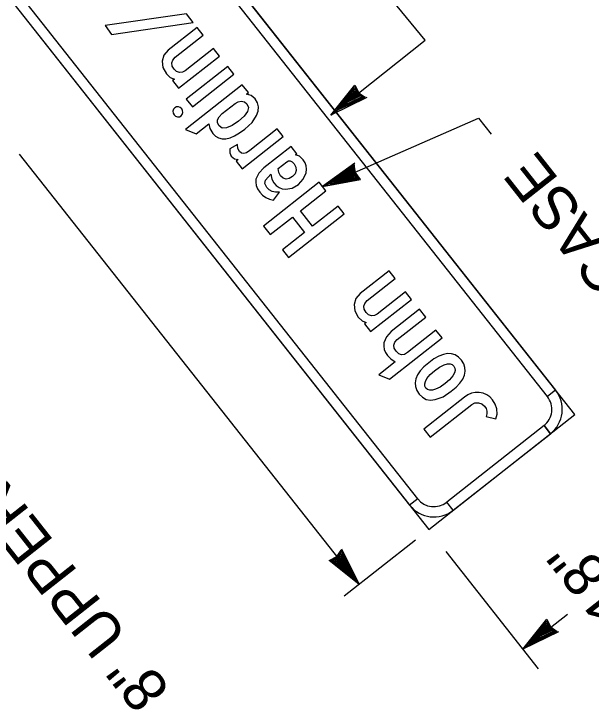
# Model space of a CAD drawing. Extents: x 671946 to 673995, y 1673066 to 1674936.
# Drawn here: x 672492.5 to 672548.4, y 1673764.2 to 1673831.7 of the extents above; entities that cross this region are included whole.
import ezdxf

# ---------------------------------------------------------------- set-up
doc = ezdxf.new("R2010")
doc.units = 0
doc.layers.add('C-ANNO-SYMB', color=7, linetype='Continuous')
doc.layers.add('Level 1', color=7, linetype='Continuous')

msp = doc.modelspace()

# ---------------------------------------------------------------- linework, layer by layer
at = {"layer": 'C-ANNO-SYMB'}
for p, q in [((672546.828, 1673792.897), (672468.821, 1673891.846)), ((672470.678, 1673889.49), (672544.97, 1673795.253)), ((672544.185, 1673794.634), (672469.893, 1673888.871)), ((672454.685, 1673880.702), (672532.692, 1673781.753)), ((672531.62, 1673784.728), (672457.328, 1673878.966)), ((672456.543, 1673878.347), (672530.835, 1673784.109)), ((672544.97, 1673795.253), (672544.185, 1673794.634)), ((672544.97, 1673795.253), (672544.185, 1673794.634)), ((672544.185, 1673794.634), (672544.185, 1673794.634)), ((672544.185, 1673794.634), (672544.185, 1673794.634)), ((672532.692, 1673781.753), (672546.828, 1673792.897)), ((672546.828, 1673792.897), (672546.828, 1673792.897)), ((672546.828, 1673792.897), (672546.828, 1673792.897)), ((672543.853, 1673791.825), (672534.429, 1673784.396)), ((672543.853, 1673791.825), (672544.472, 1673791.04)), ((672544.472, 1673791.04), (672543.853, 1673791.825)), ((672543.853, 1673791.825), (672544.472, 1673791.04)), ((672535.048, 1673783.611), (672544.472, 1673791.04)), ((672531.62, 1673784.728), (672530.835, 1673784.109)), ((672531.62, 1673784.728), (672530.835, 1673784.109)), ((672535.048, 1673783.611), (672534.429, 1673784.396)), ((672534.429, 1673784.396), (672534.429, 1673784.396)), ((672534.429, 1673784.396), (672534.429, 1673784.396)), ((672535.048, 1673783.611), (672534.429, 1673784.396))]:
    msp.add_line(p, q, dxfattribs=at)
for points in [[(672509.876, 1673830.886), (672509.215, 1673831.723), (672501.355, 1673830.605), (672501.971, 1673829.732)], [(672512.433, 1673827.642), (672511.85, 1673828.382), (672509.104, 1673826.218), (672508.832, 1673826.07), (672508.542, 1673826.045), (672508.264, 1673826.142), (672508.026, 1673826.356), (672507.841, 1673826.676), (672507.797, 1673826.977), (672507.897, 1673827.256), (672508.142, 1673827.517), (672510.849, 1673829.651), (672510.247, 1673830.415), (672507.455, 1673828.214), (672507.027, 1673827.725), (672506.859, 1673827.137), (672506.944, 1673826.516), (672507.271, 1673825.927), (672507.645, 1673825.569), (672508.048, 1673825.401), (672507.872, 1673825.263), (672508.463, 1673824.513)], [(672513.819, 1673825.883), (672513.219, 1673826.644), (672509.203, 1673823.478), (672509.803, 1673822.717)], [(672508.701, 1673821.848), (672508.819, 1673821.986), (672508.868, 1673822.163), (672508.849, 1673822.35), (672508.758, 1673822.52), (672508.612, 1673822.653), (672508.437, 1673822.719), (672508.257, 1673822.713), (672508.088, 1673822.626), (672507.963, 1673822.482), (672507.907, 1673822.302), (672507.925, 1673822.111), (672508.017, 1673821.936), (672508.166, 1673821.806), (672508.348, 1673821.749), (672508.536, 1673821.761)], [(672518.586, 1673819.836), (672518.003, 1673820.576), (672515.351, 1673818.474), (672515.041, 1673818.273), (672514.77, 1673818.19), (672514.539, 1673818.227), (672514.344, 1673818.385), (672514.207, 1673818.682), (672514.177, 1673819.076), (672513.41, 1673818.664), (672513.425, 1673818.255), (672513.562, 1673817.948), (672513.867, 1673817.693), (672514.231, 1673817.602), (672514.034, 1673817.447), (672514.617, 1673816.707)], [(672524.48, 1673812.36), (672523.897, 1673813.1), (672521.423, 1673811.149), (672520.256, 1673812.63), (672522.73, 1673814.58), (672522.081, 1673815.404), (672516.69, 1673811.154), (672517.339, 1673810.33), (672519.501, 1673812.034), (672520.668, 1673810.554), (672518.506, 1673808.85), (672519.089, 1673808.11)], [(672531.024, 1673804.06), (672530.441, 1673804.799), (672527.696, 1673802.635), (672527.424, 1673802.488), (672527.133, 1673802.462), (672526.856, 1673802.559), (672526.617, 1673802.773), (672526.432, 1673803.093), (672526.388, 1673803.394), (672526.489, 1673803.673), (672526.734, 1673803.934), (672529.441, 1673806.068), (672528.838, 1673806.832), (672526.047, 1673804.632), (672525.619, 1673804.142), (672525.45, 1673803.554), (672525.536, 1673802.933), (672525.863, 1673802.344), (672526.237, 1673801.986), (672526.639, 1673801.818), (672526.464, 1673801.68), (672527.055, 1673800.93)], [(672529.04, 1673800.93), (672528.578, 1673800.43), (672528.349, 1673799.839), (672528.33, 1673799.514), (672528.379, 1673799.199), (672528.501, 1673798.893), (672528.691, 1673798.601), (672529.01, 1673798.287), (672529.444, 1673798.002), (672527.866, 1673796.759), (672528.889, 1673796.315), (672533.971, 1673800.321), (672533.388, 1673801.061), (672530.643, 1673798.897), (672530.34, 1673798.72), (672530.051, 1673798.683), (672529.781, 1673798.785), (672529.523, 1673799.029), (672529.343, 1673799.34), (672529.301, 1673799.634), (672529.403, 1673799.909), (672529.643, 1673800.166), (672532.388, 1673802.33), (672531.785, 1673803.094)], [(672539.176, 1673792.48), (672539.298, 1673792.946), (672539.274, 1673793.438), (672539.133, 1673793.9), (672538.872, 1673794.321), (672538.603, 1673794.605), (672538.298, 1673794.82), (672537.958, 1673794.959), (672537.578, 1673795.029), (672537.196, 1673795.028), (672536.83, 1673794.953), (672536.483, 1673794.809), (672536.152, 1673794.593), (672532.201, 1673791.478), (672532.818, 1673790.695), (672536.847, 1673793.872), (672537.155, 1673794.028), (672537.498, 1673794.044), (672537.828, 1673793.932), (672538.088, 1673793.703), (672538.232, 1673793.474), (672538.305, 1673793.231), (672538.31, 1673792.976), (672538.246, 1673792.708)]]:
    msp.add_lwpolyline(points, close=True, dxfattribs=at)
for points in [[(672515.233, 1673824.1), (672514.628, 1673824.867), (672509.127, 1673820.529), (672510.147, 1673820.092), (672511.396, 1673821.076), (672511.483, 1673820.622), (672511.764, 1673820.15), (672512.032, 1673819.879), (672512.331, 1673819.703), (672512.667, 1673819.616), (672513.036, 1673819.624), (672513.443, 1673819.719), (672513.883, 1673819.909), (672514.359, 1673820.188), (672514.866, 1673820.558), (672515.569, 1673821.211), (672516.019, 1673821.871), (672516.174, 1673822.306), (672516.199, 1673822.723), (672516.099, 1673823.121), (672515.87, 1673823.499), (672515.5, 1673823.808), (672515.043, 1673823.951), (672515.233, 1673824.1)], [(672513.931, 1673823.048), (672514.212, 1673823.208), (672514.518, 1673823.264), (672514.838, 1673823.206), (672515.08, 1673823.011), (672515.222, 1673822.665), (672515.132, 1673822.269), (672514.817, 1673821.826), (672514.27, 1673821.331), (672513.634, 1673820.894), (672513.105, 1673820.671), (672512.688, 1673820.667), (672512.378, 1673820.88), (672512.228, 1673821.169), (672512.228, 1673821.464), (672512.38, 1673821.761), (672512.681, 1673822.062), (672513.931, 1673823.048)], [(672519.904, 1673818.166), (672519.346, 1673818.873), (672516.722, 1673816.804), (672516.215, 1673816.284), (672515.955, 1673815.723), (672515.929, 1673815.404), (672515.977, 1673815.089), (672516.106, 1673814.772), (672516.311, 1673814.461), (672516.592, 1673814.162), (672516.907, 1673813.932), (672517.262, 1673813.768), (672517.648, 1673813.672), (672518.221, 1673814.44), (672517.846, 1673814.441), (672517.512, 1673814.518), (672517.229, 1673814.673), (672516.992, 1673814.901), (672516.801, 1673815.283), (672516.859, 1673815.621), (672517.398, 1673816.19), (672517.48, 1673815.714), (672517.668, 1673815.348), (672517.915, 1673815.09), (672518.185, 1673814.904), (672518.484, 1673814.787), (672518.806, 1673814.738), (672519.442, 1673814.845), (672520.059, 1673815.204), (672520.537, 1673815.716), (672520.798, 1673816.332), (672520.847, 1673816.673), (672520.818, 1673816.996), (672520.716, 1673817.298), (672520.536, 1673817.58), (672520.159, 1673817.949), (672519.795, 1673818.08), (672519.904, 1673818.166)], [(672518.107, 1673816.749), (672518.936, 1673817.403), (672519.106, 1673817.489), (672519.28, 1673817.483), (672519.458, 1673817.386), (672519.639, 1673817.197), (672519.824, 1673816.871), (672519.858, 1673816.542), (672519.752, 1673816.233), (672519.502, 1673815.964), (672519.172, 1673815.765), (672518.866, 1673815.709), (672518.586, 1673815.798), (672518.328, 1673816.033), (672518.159, 1673816.356), (672518.107, 1673816.749)], [(672532.682, 1673797.918), (672532.221, 1673797.518), (672531.855, 1673797.122), (672531.592, 1673796.732), (672531.422, 1673796.35), (672531.358, 1673795.972), (672531.388, 1673795.602), (672531.52, 1673795.237), (672531.747, 1673794.881), (672532.068, 1673794.564), (672532.435, 1673794.368), (672532.85, 1673794.293), (672533.308, 1673794.338), (672534.067, 1673794.618), (672534.868, 1673795.145), (672535.338, 1673795.551), (672535.707, 1673795.946), (672535.979, 1673796.335), (672536.148, 1673796.716), (672536.223, 1673797.088), (672536.194, 1673797.454), (672536.068, 1673797.813), (672535.843, 1673798.163), (672535.558, 1673798.461), (672535.238, 1673798.667), (672534.89, 1673798.779), (672534.508, 1673798.796), (672534.1, 1673798.718), (672533.657, 1673798.546), (672533.187, 1673798.279), (672532.682, 1673797.918)], [(672533.251, 1673797.141), (672533.732, 1673797.477), (672534.183, 1673797.706), (672534.488, 1673797.794), (672534.747, 1673797.805), (672534.961, 1673797.739), (672535.125, 1673797.595), (672535.228, 1673797.4), (672535.242, 1673797.178), (672535.175, 1673796.929), (672535.018, 1673796.657), (672534.702, 1673796.272), (672534.267, 1673795.887), (672533.797, 1673795.559), (672533.35, 1673795.341), (672533.049, 1673795.254), (672532.79, 1673795.245), (672532.58, 1673795.312), (672532.413, 1673795.457), (672532.315, 1673795.648), (672532.298, 1673795.867), (672532.366, 1673796.111), (672532.512, 1673796.381), (672532.829, 1673796.762), (672533.251, 1673797.141)]]:
    msp.add_lwpolyline(points, dxfattribs=at)
for centre, radius, start, end in [((672542.614, 1673793.396), 3, 308.25039, 38.2506), ((672542.614, 1673793.396), 2, 308.25039, 38.2506), ((672533.191, 1673785.966), 2, 218.25075, 308.25039), ((672533.191, 1673785.966), 3, 218.25075, 308.25039)]:
    msp.add_arc(centre, radius, start, end, dxfattribs=at)
at = {"layer": 'Level 1'}
for p, q in [((672523.213, 1673821.923), (672525.533, 1673824.833)), ((672523.431, 1673822.159), (672525.514, 1673824.684)), ((672523.782, 1673822.435), (672525.512, 1673824.516)), ((672525.512, 1673824.516), (672525.65, 1673824.256)), ((672525.514, 1673824.684), (672525.856, 1673824.119)), ((672525.533, 1673824.833), (672525.925, 1673824.073)), ((672524.001, 1673822.535), (672525.555, 1673824.251)), ((672524.072, 1673822.658), (672525.514, 1673824.384)), ((672524.506, 1673822.998), (672525.5, 1673824.106)), ((672526.016, 1673823.745), (672524.506, 1673822.998)), ((672524.893, 1673823.267), (672525.464, 1673823.979)), ((672525.853, 1673823.784), (672524.893, 1673823.267)), ((672525.558, 1673824.119), (672525.052, 1673823.361)), ((672525.229, 1673823.563), (672525.494, 1673823.902)), ((672525.746, 1673823.834), (672525.229, 1673823.563)), ((672525.464, 1673823.979), (672525.746, 1673823.834)), ((672525.494, 1673823.902), (672525.576, 1673823.837)), ((672525.5, 1673824.106), (672525.853, 1673823.784)), ((672525.514, 1673824.384), (672526.195, 1673823.686)), ((672525.555, 1673824.251), (672526.016, 1673823.745)), ((672525.934, 1673823.848), (672525.558, 1673824.119)), ((672525.576, 1673823.837), (672525.934, 1673823.848)), ((672525.65, 1673824.256), (672526.195, 1673823.686)), ((672525.856, 1673824.119), (672526.527, 1673823.646)), ((672525.925, 1673824.073), (672526.167, 1673823.764)), ((672526.167, 1673823.764), (672526.481, 1673823.576)), ((672526.674, 1673823.628), (672523.213, 1673821.923)), ((672526.316, 1673823.614), (672523.473, 1673822.191)), ((672526.481, 1673823.576), (672523.633, 1673822.283)), ((672526.195, 1673823.686), (672524.001, 1673822.535)), ((672526.195, 1673823.686), (672524.072, 1673822.658)), ((672525.052, 1673823.361), (672524.799, 1673823.26)), ((672526.527, 1673823.646), (672526.307, 1673823.71)), ((672526.307, 1673823.71), (672526.316, 1673823.614)), ((672525.935, 1673776.427), (672493.051, 1673818.139)), ((672525.525, 1673817.262), (672522.405, 1673814.992)), ((672525.39, 1673817.116), (672522.92, 1673815.197)), ((672525.409, 1673816.75), (672525.39, 1673817.116)), ((672525.473, 1673817.123), (672525.427, 1673816.9)), ((672525.579, 1673816.309), (672525.473, 1673817.123)), ((672525.346, 1673816.951), (672522.763, 1673815.097)), ((672525.354, 1673816.811), (672523.314, 1673815.405)), ((672525.354, 1673816.811), (672523.456, 1673815.41)), ((672525.322, 1673816.625), (672523.959, 1673815.636)), ((672525.282, 1673816.463), (672524.377, 1673815.854)), ((672525.275, 1673816.345), (672524.795, 1673816.013)), ((672525.2, 1673816.193), (672525.376, 1673816.505)), ((672525.273, 1673816.028), (672525.275, 1673816.345)), ((672525.402, 1673816), (672525.282, 1673816.463)), ((672525.556, 1673815.982), (672525.322, 1673816.625)), ((672525.427, 1673816.9), (672525.346, 1673816.951)), ((672525.604, 1673816.064), (672525.354, 1673816.811)), ((672525.655, 1673815.883), (672525.354, 1673816.811)), ((672525.376, 1673816.505), (672525.441, 1673816.046)), ((672525.571, 1673816.392), (672525.409, 1673816.75)), ((672526.061, 1673815.691), (672525.571, 1673816.392)), ((672522.405, 1673814.992), (672526.061, 1673815.691)), ((672522.716, 1673815.075), (672525.921, 1673815.744)), ((672522.886, 1673815.267), (672523.634, 1673815.777)), ((672523.123, 1673815.257), (672525.77, 1673815.82)), ((672523.634, 1673815.777), (672523.123, 1673815.257)), ((672523.314, 1673815.405), (672525.556, 1673815.982)), ((672523.456, 1673815.41), (672525.655, 1673815.883)), ((672523.851, 1673815.616), (672524.238, 1673815.905)), ((672524.327, 1673815.774), (672523.851, 1673815.616)), ((672523.959, 1673815.636), (672525.402, 1673816)), ((672524.534, 1673815.951), (672524.327, 1673815.774)), ((672524.377, 1673815.854), (672525.273, 1673816.028)), ((672525.441, 1673816.046), (672524.534, 1673815.951)), ((672524.795, 1673816.013), (672525.219, 1673816.09)), ((672525.219, 1673816.09), (672525.2, 1673816.193)), ((672525.921, 1673815.744), (672525.579, 1673816.309)), ((672525.77, 1673815.82), (672525.604, 1673816.064)), ((672522.92, 1673815.197), (672522.716, 1673815.075)), ((672522.763, 1673815.097), (672522.886, 1673815.267)), ((672531.395, 1673780.731), (672524.491, 1673775.288)), ((672524.232, 1673779.888), (672525.935, 1673776.427)), ((672523.475, 1673778.728), (672524.174, 1673779.409)), ((672523.604, 1673778.865), (672524.174, 1673779.409)), ((672523.609, 1673778.77), (672524.115, 1673779.23)), ((672523.741, 1673779.07), (672524.214, 1673779.741)), ((672523.786, 1673779.14), (672524.096, 1673779.382)), ((672524.096, 1673779.382), (672524.284, 1673779.696)), ((672524.115, 1673779.23), (672524.861, 1673777.72)), ((672524.214, 1673779.741), (672524.15, 1673779.522)), ((672524.15, 1673779.522), (672524.246, 1673779.53)), ((672524.174, 1673779.409), (672525.2, 1673777.286)), ((672524.174, 1673779.409), (672525.324, 1673777.214)), ((672524.246, 1673779.53), (672525.668, 1673776.686)), ((672524.284, 1673779.696), (672525.576, 1673776.847)), ((672534.338, 1673779.605), (672543.294, 1673768.245)), ((672523.027, 1673778.748), (672523.786, 1673779.14)), ((672525.935, 1673776.427), (672523.027, 1673778.748)), ((672523.175, 1673778.73), (672523.741, 1673779.07)), ((672525.699, 1673776.644), (672523.175, 1673778.73)), ((672523.344, 1673778.727), (672523.604, 1673778.865)), ((672525.424, 1673776.996), (672523.344, 1673778.727)), ((672525.2, 1673777.286), (672523.475, 1673778.728)), ((672525.324, 1673777.214), (672523.609, 1673778.77)), ((672524.012, 1673779.149), (672523.74, 1673778.773)), ((672523.74, 1673778.773), (672524.499, 1673778.267)), ((672523.753, 1673778.714), (672524.075, 1673779.068)), ((672524.861, 1673777.72), (672523.753, 1673778.714)), ((672523.88, 1673778.679), (672524.026, 1673778.96)), ((672524.592, 1673778.107), (672523.88, 1673778.679)), ((672523.957, 1673778.709), (672524.022, 1673778.791)), ((672524.297, 1673778.443), (672523.957, 1673778.709)), ((672524.022, 1673778.791), (672524.012, 1673779.149)), ((672524.026, 1673778.96), (672524.297, 1673778.443)), ((672524.075, 1673779.068), (672524.592, 1673778.107)), ((672524.499, 1673778.267), (672524.599, 1673778.013)), ((672524.599, 1673778.013), (672524.947, 1673777.652)), ((672524.947, 1673777.652), (672524.739, 1673778.088)), ((672525.638, 1673776.894), (672525.213, 1673777.693)), ((672525.213, 1673777.693), (672525.424, 1673776.996)), ((672525.576, 1673776.847), (672525.699, 1673776.644)), ((672525.668, 1673776.686), (672525.638, 1673776.894)), ((672541.8, 1673770.141), (672546.125, 1673773.551)), ((672541.8, 1673770.141), (672544.121, 1673773.049)), ((672542.017, 1673770.377), (672544.103, 1673772.901)), ((672542.369, 1673770.652), (672544.1, 1673772.732)), ((672542.588, 1673770.752), (672544.143, 1673772.467)), ((672542.659, 1673770.876), (672544.102, 1673772.601)), ((672544.1, 1673772.732), (672544.238, 1673772.472)), ((672544.102, 1673772.601), (672544.782, 1673771.902)), ((672544.103, 1673772.901), (672544.444, 1673772.335)), ((672544.121, 1673773.049), (672544.513, 1673772.29)), ((672544.143, 1673772.467), (672544.603, 1673771.961)), ((672544.238, 1673772.472), (672544.782, 1673771.902)), ((672545.261, 1673771.844), (672541.8, 1673770.141)), ((672544.903, 1673771.83), (672542.06, 1673770.408)), ((672545.069, 1673771.792), (672542.22, 1673770.5)), ((672544.782, 1673771.902), (672542.588, 1673770.752)), ((672544.782, 1673771.902), (672542.659, 1673770.876)), ((672543.093, 1673771.215), (672544.088, 1673772.323)), ((672544.603, 1673771.961), (672543.093, 1673771.215)), ((672543.48, 1673771.484), (672544.052, 1673772.196)), ((672544.441, 1673772.001), (672543.48, 1673771.484)), ((672544.146, 1673772.336), (672543.64, 1673771.578)), ((672543.816, 1673771.779), (672544.082, 1673772.119)), ((672544.333, 1673772.05), (672543.816, 1673771.779)), ((672544.052, 1673772.196), (672544.333, 1673772.05)), ((672544.082, 1673772.119), (672544.164, 1673772.054)), ((672544.088, 1673772.323), (672544.441, 1673772.001)), ((672544.522, 1673772.065), (672544.146, 1673772.336)), ((672544.164, 1673772.054), (672544.522, 1673772.065)), ((672544.444, 1673772.335), (672545.114, 1673771.862)), ((672544.513, 1673772.29), (672544.755, 1673771.98)), ((672544.755, 1673771.98), (672545.069, 1673771.792)), ((672545.114, 1673771.862), (672544.895, 1673771.926)), ((672544.895, 1673771.926), (672544.903, 1673771.83)), ((672543.387, 1673771.477), (672543.025, 1673771.129)), ((672543.025, 1673771.129), (672543.461, 1673771.337)), ((672543.64, 1673771.578), (672543.387, 1673771.477)), ((672542.22, 1673770.5), (672542.017, 1673770.377)), ((672542.06, 1673770.408), (672542.267, 1673770.438)), ((672542.267, 1673770.438), (672543.066, 1673770.863)), ((672543.066, 1673770.863), (672542.369, 1673770.652))]:
    msp.add_line(p, q, dxfattribs=at)
for points in [[(672523.213, 1673821.923), (672532.326, 1673829.183), (672529.188, 1673833.04)], [(672522.405, 1673814.992), (672537.514, 1673821.629), (672538.736, 1673820.078)]]:
    msp.add_lwpolyline(points, dxfattribs=at)

# ---------------------------------------------------------------- texts
for s, p in [('8" UPPERCASE', (672568.657, 1673786.13)), ('8" UPPERCASE', (672507.761, 1673766.257)), ('18"', (672552.344, 1673774.979))]:
    msp.add_text(s, height=4.2, rotation=128.25054, dxfattribs=at).set_placement(p)

doc.saveas('drawing.dxf')
